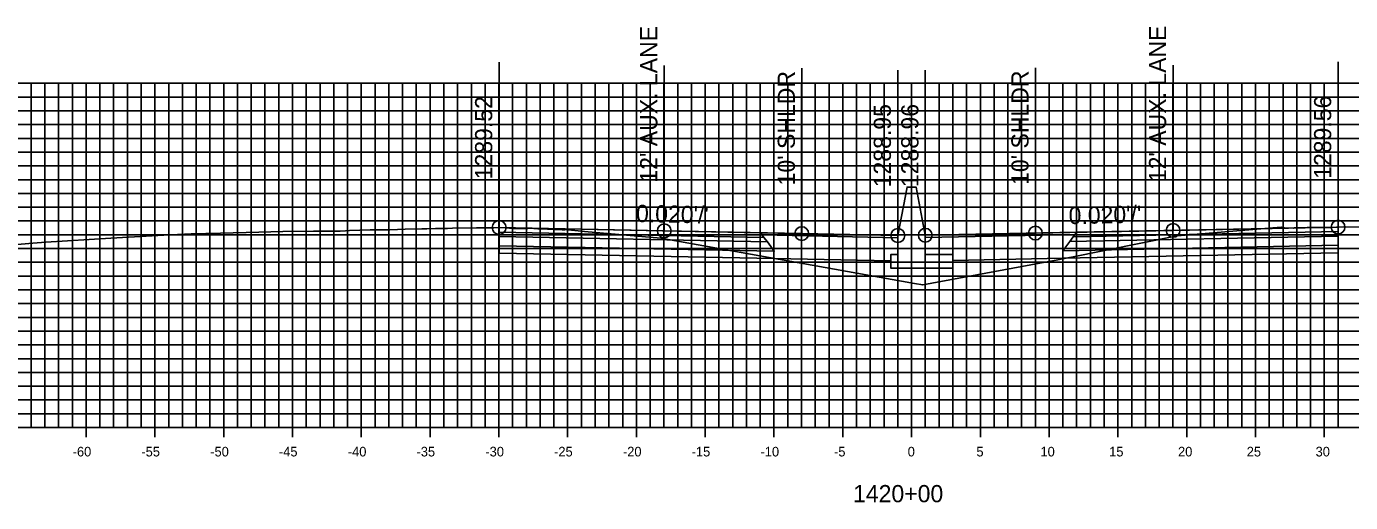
# Model space of a CAD drawing. Extents: x 674939 to 678919, y 750652 to 765176.
# Drawn here: x 677874.2 to 677970.4, y 757657.1 to 757691.7 of the extents above; entities that cross this region are included whole.
import ezdxf

# ---------------------------------------------------------------- set-up
doc = ezdxf.new("R2010")
doc.units = 0
for name, color, linetype in [('R_Alt Surface', 7, 'Continuous'), ('R_Axis', 7, 'Continuous'), ('R_Axis Annot', 7, 'Continuous'), ('R_Exist Surface', 7, 'Continuous'), ('R_Fin Surface', 7, 'Continuous'), ('R_Grid', 7, 'Continuous'), ('R_No Plot', 7, 'Continuous'), ('R_Proposed Road', 7, 'Continuous'), ('R_Xsect Elev', 7, 'Continuous'), ('R_Xsect Slope', 7, 'Continuous')]:
    doc.layers.add(name, color=color, linetype=linetype)

msp = doc.modelspace()

# ---------------------------------------------------------------- linework, layer by layer
at = {"layer": 'R_Alt Surface'}
for points in [[(677908.553, 757676.746), (677908.553, 757676.416), (677928.053, 757676.026), (677927.803, 757676.361)], [(677908.553, 757676.416), (677908.553, 757675.756), (677928.553, 757675.356), (677928.053, 757676.026)], [(677969.538, 757676.45), (677969.538, 757675.79), (677949.538, 757675.39), (677950.038, 757676.06)], [(677969.538, 757676.78), (677969.538, 757676.45), (677950.038, 757676.06), (677950.288, 757676.395)]]:
    msp.add_lwpolyline(points, close=True, dxfattribs=at)
for points in [[(677908.553, 757675.756), (677908.553, 757675.216), (677928.553, 757674.816), (677937.033, 757674.646)], [(677969.538, 757675.79), (677969.538, 757675.25), (677949.538, 757674.85), (677941.533, 757674.69)]]:
    msp.add_lwpolyline(points, dxfattribs=at)
at = {"layer": 'R_Axis'}
for p, q in [((677878.533, 757661.851), (677878.533, 757663.251)), ((677883.533, 757661.851), (677883.533, 757663.251)), ((677888.533, 757661.851), (677888.533, 757663.251)), ((677893.533, 757661.851), (677893.533, 757663.251)), ((677898.533, 757661.851), (677898.533, 757663.251)), ((677903.533, 757661.851), (677903.533, 757663.251)), ((677908.533, 757661.851), (677908.533, 757663.251)), ((677913.533, 757661.851), (677913.533, 757663.251)), ((677918.533, 757661.851), (677918.533, 757663.251)), ((677923.533, 757661.851), (677923.533, 757663.251)), ((677928.533, 757661.851), (677928.533, 757663.251)), ((677933.533, 757661.851), (677933.533, 757663.251)), ((677938.533, 757661.851), (677938.533, 757663.251)), ((677943.533, 757661.851), (677943.533, 757663.251)), ((677948.533, 757661.851), (677948.533, 757663.251)), ((677953.533, 757661.851), (677953.533, 757663.251)), ((677958.533, 757661.851), (677958.533, 757663.251)), ((677963.533, 757661.851), (677963.533, 757663.251)), ((677968.533, 757661.851), (677968.533, 757663.251)), ((677838.533, 757662.551), (678038.533, 757662.551))]:
    msp.add_line(p, q, dxfattribs=at)
at = {"layer": 'R_Exist Surface'}
msp.add_lwpolyline([(677872.957, 757675.802), (677874.657, 757675.934), (677875.604, 757676.002), (677880.325, 757676.291), (677884.19, 757676.51), (677886.177, 757676.609), (677888.289, 757676.664), (677891.094, 757676.74), (677892.832, 757676.786), (677895.068, 757676.809), (677896.281, 757676.823), (677896.777, 757676.808), (677897.005, 757676.806), (677897.377, 757676.843), (677897.68, 757676.865), (677899.17, 757676.902), (677900.005, 757676.918), (677900.233, 757676.914), (677900.605, 757676.897), (677901.722, 757676.945), (677902.936, 757676.986), (677903.308, 757676.983), (677903.929, 757677.011), (677904.798, 757677.008), (677905.17, 757677.027), (677906.916, 757677.052), (677908.157, 757677.059), (677908.5, 757677.071), (677908.553, 757677.076), (677908.576, 757677.078), (677908.605, 757677.079), (677908.985, 757677.045), (677909.605, 757677.005), (677909.977, 757676.993), (677910.509, 757676.991), (677910.757, 757677.019), (677911.377, 757676.98), (677912.061, 757676.953), (677913.146, 757676.909), (677913.298, 757676.918), (677913.348, 757676.936), (677914.762, 757676.782), (677920.31, 757676.313), (677928.857, 757674.768), (677929.68, 757674.626), (677938.758, 757673.009), (677939.346, 757672.907), (677949.161, 757674.738), (677950.018, 757674.899), (677950.044, 757674.904), (677957.83, 757676.466), (677964.511, 757677.039), (677965.396, 757677.103), (677965.567, 757677.065), (677965.642, 757677.056), (677966.287, 757677.038), (677966.365, 757677.045), (677966.481, 757677.047), (677967.288, 757677.084), (677967.714, 757677.085), (677969.004, 757677.089), (677969.433, 757677.102), (677969.538, 757677.11), (677969.549, 757677.111), (677969.926, 757677.124), (677971.247, 757677.099)], dxfattribs=at)
at = {"layer": 'R_Fin Surface'}
for points in [[(677937.533, 757676.496), (677930.553, 757676.636), (677920.553, 757676.836), (677908.553, 757677.076)], [(677969.538, 757677.11), (677957.538, 757676.87), (677947.538, 757676.67), (677939.533, 757676.51)]]:
    msp.add_lwpolyline(points, dxfattribs=at)
for points in [[(677908.553, 757677.076), (677908.553, 757676.746), (677927.803, 757676.361), (677927.553, 757676.696)], [(677927.553, 757676.696), (677937.533, 757676.496), (677937.537, 757676.338), (677927.672, 757676.536)], [(677950.419, 757676.57), (677939.533, 757676.353), (677939.533, 757676.51), (677950.538, 757676.73)], [(677969.538, 757677.11), (677969.538, 757676.78), (677950.288, 757676.395), (677950.538, 757676.73)]]:
    msp.add_lwpolyline(points, close=True, dxfattribs=at)
at = {"layer": 'R_Grid'}
for p, q in [((677838.533, 757687.551), (678038.533, 757687.551)), ((677874.533, 757662.551), (677874.533, 757687.551)), ((677875.533, 757662.551), (677875.533, 757687.551)), ((677876.533, 757662.551), (677876.533, 757687.551)), ((677877.533, 757662.551), (677877.533, 757687.551)), ((677878.533, 757662.551), (677878.533, 757687.551)), ((677879.533, 757662.551), (677879.533, 757687.551)), ((677880.533, 757662.551), (677880.533, 757687.551)), ((677881.533, 757662.551), (677881.533, 757687.551)), ((677882.533, 757662.551), (677882.533, 757687.551)), ((677883.533, 757662.551), (677883.533, 757687.551)), ((677884.533, 757662.551), (677884.533, 757687.551)), ((677885.533, 757662.551), (677885.533, 757687.551)), ((677886.533, 757662.551), (677886.533, 757687.551)), ((677887.533, 757662.551), (677887.533, 757687.551)), ((677888.533, 757662.551), (677888.533, 757687.551)), ((677889.533, 757662.551), (677889.533, 757687.551)), ((677890.533, 757662.551), (677890.533, 757687.551)), ((677891.533, 757662.551), (677891.533, 757687.551)), ((677892.533, 757662.551), (677892.533, 757687.551)), ((677893.533, 757662.551), (677893.533, 757687.551)), ((677894.533, 757662.551), (677894.533, 757687.551)), ((677895.533, 757662.551), (677895.533, 757687.551)), ((677896.533, 757662.551), (677896.533, 757687.551)), ((677897.533, 757662.551), (677897.533, 757687.551)), ((677898.533, 757662.551), (677898.533, 757687.551)), ((677899.533, 757662.551), (677899.533, 757687.551)), ((677900.533, 757662.551), (677900.533, 757687.551)), ((677901.533, 757662.551), (677901.533, 757687.551)), ((677902.533, 757662.551), (677902.533, 757687.551)), ((677903.533, 757662.551), (677903.533, 757687.551)), ((677904.533, 757662.551), (677904.533, 757687.551)), ((677905.533, 757662.551), (677905.533, 757687.551)), ((677906.533, 757662.551), (677906.533, 757687.551)), ((677907.533, 757662.551), (677907.533, 757687.551)), ((677908.533, 757662.551), (677908.533, 757687.551)), ((677909.533, 757662.551), (677909.533, 757687.551)), ((677910.533, 757662.551), (677910.533, 757687.551)), ((677911.533, 757662.551), (677911.533, 757687.551)), ((677912.533, 757662.551), (677912.533, 757687.551)), ((677913.533, 757662.551), (677913.533, 757687.551)), ((677914.533, 757662.551), (677914.533, 757687.551)), ((677915.533, 757662.551), (677915.533, 757687.551)), ((677916.533, 757662.551), (677916.533, 757687.551)), ((677917.533, 757662.551), (677917.533, 757687.551)), ((677918.533, 757662.551), (677918.533, 757687.551)), ((677919.533, 757662.551), (677919.533, 757687.551)), ((677920.533, 757662.551), (677920.533, 757687.551)), ((677921.533, 757662.551), (677921.533, 757687.551)), ((677922.533, 757662.551), (677922.533, 757687.551)), ((677923.533, 757662.551), (677923.533, 757687.551)), ((677924.533, 757662.551), (677924.533, 757687.551)), ((677925.533, 757662.551), (677925.533, 757687.551)), ((677926.533, 757662.551), (677926.533, 757687.551)), ((677927.533, 757662.551), (677927.533, 757687.551)), ((677928.533, 757662.551), (677928.533, 757687.551)), ((677929.533, 757662.551), (677929.533, 757687.551)), ((677930.533, 757662.551), (677930.533, 757687.551)), ((677931.533, 757662.551), (677931.533, 757687.551)), ((677932.533, 757662.551), (677932.533, 757687.551)), ((677933.533, 757662.551), (677933.533, 757687.551)), ((677934.533, 757662.551), (677934.533, 757687.551)), ((677935.533, 757662.551), (677935.533, 757687.551)), ((677936.533, 757662.551), (677936.533, 757687.551)), ((677937.533, 757662.551), (677937.533, 757687.551)), ((677938.533, 757662.551), (677938.533, 757687.551)), ((677939.533, 757662.551), (677939.533, 757687.551)), ((677940.533, 757662.551), (677940.533, 757687.551)), ((677941.533, 757662.551), (677941.533, 757687.551)), ((677942.533, 757662.551), (677942.533, 757687.551)), ((677943.533, 757662.551), (677943.533, 757687.551)), ((677944.533, 757662.551), (677944.533, 757687.551)), ((677945.533, 757662.551), (677945.533, 757687.551)), ((677946.533, 757662.551), (677946.533, 757687.551)), ((677947.533, 757662.551), (677947.533, 757687.551)), ((677948.533, 757662.551), (677948.533, 757687.551)), ((677949.533, 757662.551), (677949.533, 757687.551)), ((677950.533, 757662.551), (677950.533, 757687.551)), ((677951.533, 757662.551), (677951.533, 757687.551)), ((677952.533, 757662.551), (677952.533, 757687.551)), ((677953.533, 757662.551), (677953.533, 757687.551)), ((677954.533, 757662.551), (677954.533, 757687.551)), ((677955.533, 757662.551), (677955.533, 757687.551)), ((677956.533, 757662.551), (677956.533, 757687.551)), ((677957.533, 757662.551), (677957.533, 757687.551)), ((677958.533, 757662.551), (677958.533, 757687.551)), ((677959.533, 757662.551), (677959.533, 757687.551)), ((677960.533, 757662.551), (677960.533, 757687.551)), ((677961.533, 757662.551), (677961.533, 757687.551)), ((677962.533, 757662.551), (677962.533, 757687.551)), ((677963.533, 757662.551), (677963.533, 757687.551)), ((677964.533, 757662.551), (677964.533, 757687.551)), ((677965.533, 757662.551), (677965.533, 757687.551)), ((677966.533, 757662.551), (677966.533, 757687.551)), ((677967.533, 757662.551), (677967.533, 757687.551)), ((677968.533, 757662.551), (677968.533, 757687.551)), ((677969.533, 757662.551), (677969.533, 757687.551)), ((677838.533, 757686.551), (678038.533, 757686.551)), ((677838.533, 757685.551), (678038.533, 757685.551)), ((677838.533, 757684.551), (678038.533, 757684.551)), ((677838.533, 757683.551), (678038.533, 757683.551)), ((677838.533, 757682.551), (678038.533, 757682.551)), ((677838.533, 757681.551), (678038.533, 757681.551)), ((677838.533, 757680.551), (678038.533, 757680.551)), ((677838.533, 757679.551), (678038.533, 757679.551)), ((677838.533, 757678.551), (678038.533, 757678.551)), ((677838.533, 757677.551), (678038.533, 757677.551)), ((677838.533, 757676.551), (678038.533, 757676.551)), ((677838.533, 757675.551), (678038.533, 757675.551)), ((677838.533, 757674.551), (678038.533, 757674.551)), ((677838.533, 757673.551), (678038.533, 757673.551)), ((677838.533, 757672.551), (678038.533, 757672.551)), ((677838.533, 757671.551), (678038.533, 757671.551)), ((677838.533, 757670.551), (678038.533, 757670.551)), ((677838.533, 757669.551), (678038.533, 757669.551)), ((677838.533, 757668.551), (678038.533, 757668.551)), ((677838.533, 757667.551), (678038.533, 757667.551)), ((677838.533, 757666.551), (678038.533, 757666.551)), ((677838.533, 757665.551), (678038.533, 757665.551)), ((677838.533, 757664.551), (678038.533, 757664.551)), ((677838.533, 757663.551), (678038.533, 757663.551)), ((677838.533, 757662.551), (678038.533, 757662.551))]:
    msp.add_line(p, q, dxfattribs=at)
at = {"layer": 'R_No Plot'}
for centre in [(677908.553, 757677.076), (677920.553, 757676.836), (677957.538, 757676.87), (677969.538, 757677.11), (677930.553, 757676.636), (677937.533, 757676.496), (677939.533, 757676.51), (677947.538, 757676.67)]:
    msp.add_circle(centre, 0.5, dxfattribs=at)
at = {"layer": 'R_Proposed Road'}
for points in [[(677938.203, 757679.996), (677937.533, 757676.496)], [(677938.863, 757680.01), (677938.863, 757680.01), (677938.203, 757680.01), (677938.203, 757679.996)], [(677938.863, 757680.01), (677939.533, 757676.51)], [(677937.533, 757676.496), (677937.533, 757675.121), (677937.033, 757675.121), (677937.033, 757674.121), (677941.533, 757674.121), (677941.533, 757675.121), (677939.533, 757675.121), (677939.533, 757676.51)]]:
    msp.add_lwpolyline(points, dxfattribs=at)
at = {"layer": 'R_Xsect Elev'}
for p, q in [((677908.553, 757677.076), (677908.553, 757689.076)), ((677920.553, 757676.836), (677920.553, 757688.836)), ((677957.538, 757676.87), (677957.538, 757688.87)), ((677969.538, 757677.11), (677969.538, 757689.11)), ((677930.553, 757676.636), (677930.553, 757688.636)), ((677937.533, 757676.496), (677937.533, 757688.496)), ((677939.533, 757676.51), (677939.533, 757688.51)), ((677947.538, 757676.67), (677947.538, 757688.67))]:
    msp.add_line(p, q, dxfattribs=at)

# ---------------------------------------------------------------- texts
at = {"layer": 'R_Axis Annot'}
for s, height, p in [('-60', 0.7, (677877.552, 757660.451)), ('-55', 0.7, (677882.546, 757660.451)), ('-50', 0.7, (677887.552, 757660.451)), ('-45', 0.7, (677892.546, 757660.451)), ('-40', 0.7, (677897.552, 757660.451)), ('-35', 0.7, (677902.546, 757660.451)), ('-30', 0.7, (677907.552, 757660.451)), ('-25', 0.7, (677912.546, 757660.451)), ('-20', 0.7, (677917.552, 757660.451)), ('-15', 0.7, (677922.546, 757660.451)), ('-10', 0.7, (677927.552, 757660.451)), ('-5', 0.7, (677932.896, 757660.451)), ('0', 0.7, (677938.252, 757660.451)), ('5', 0.7, (677943.246, 757660.451)), ('10', 0.7, (677947.902, 757660.451)), ('15', 0.7, (677952.896, 757660.451)), ('20', 0.7, (677957.902, 757660.451)), ('25', 0.7, (677962.896, 757660.451)), ('30', 0.7, (677967.902, 757660.451)), ('1420+00', 1.25, (677934.281, 757657.126))]:
    msp.add_text(s, height=height, dxfattribs=at).set_placement(p)
at = {"layer": 'R_Xsect Elev'}
for s, p in [("12' AUX. LANE", (677957.038, 757680.37)), ("12' AUX. LANE", (677920.053, 757680.336)), ("10' SHLDR", (677930.053, 757680.136)), ("10' SHLDR", (677947.038, 757680.17)), ('1289.52', (677908.053, 757680.576)), ('1288.95', (677937.033, 757679.996)), ('1288.96', (677939.033, 757680.01)), ('1289.56', (677969.038, 757680.61))]:
    msp.add_text(s, height=1.25, rotation=90, dxfattribs=at).set_placement(p)
at = {"layer": 'R_Xsect Slope'}
for rotation, p in [(358.85424, (677918.493, 757677.477)), (1.14576, (677949.962, 757677.319))]:
    msp.add_text("0.020'/'", height=1.25, rotation=rotation, dxfattribs=at).set_placement(p)

doc.saveas('drawing.dxf')
